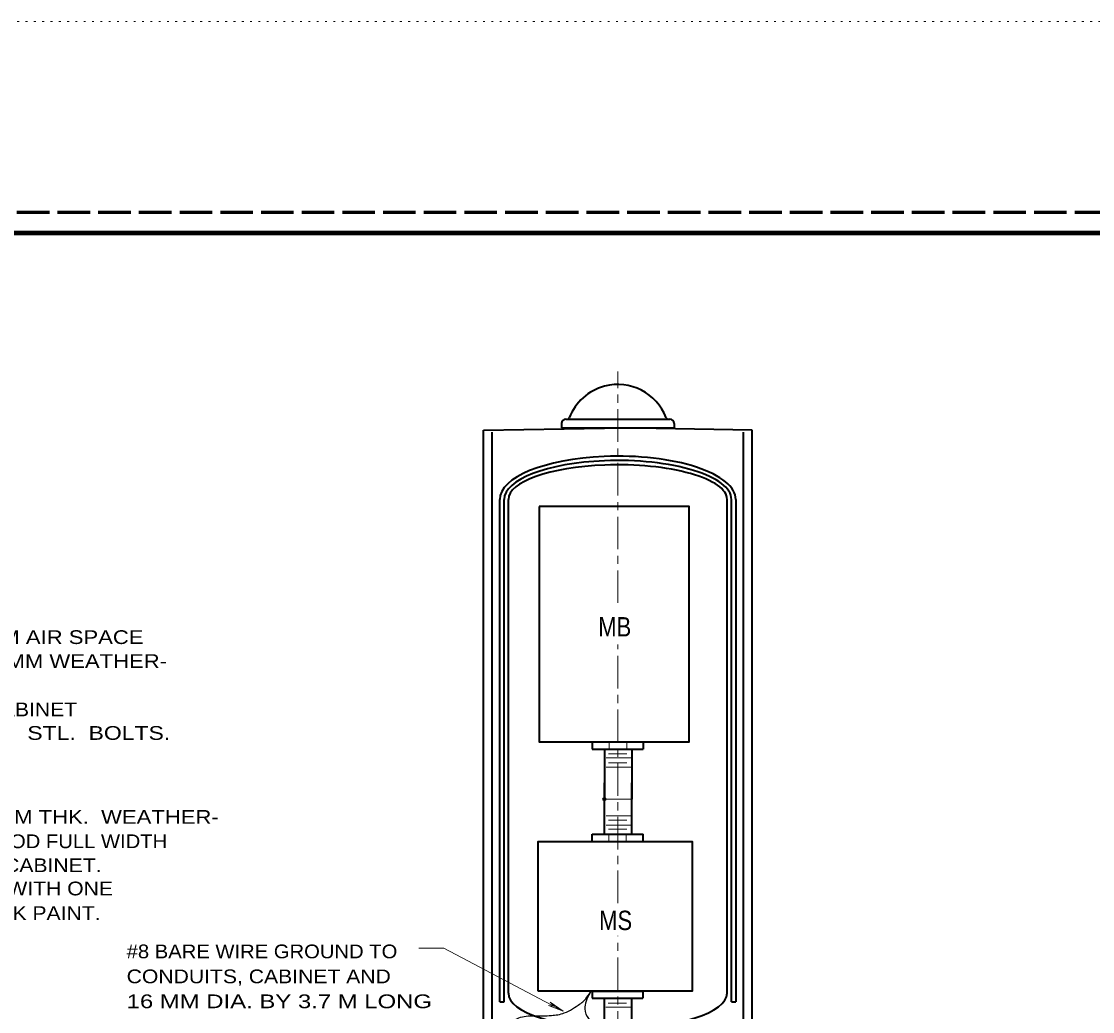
# Model space of a CAD drawing. Extents: x 312583 to 312854, y 144419 to 144597.
# Drawn here: x 312721.9 to 312781.2, y 144542 to 144596.8 of the extents above; entities that cross this region are included whole.
import ezdxf
from ezdxf.enums import TextEntityAlignment as Align

# ---------------------------------------------------------------- set-up
doc = ezdxf.new("R2010")
doc.units = 0
doc.header["$LTSCALE"] = 0.3
doc.header["$PDMODE"] = 32
doc.header["$PDSIZE"] = 0.15
for name, pattern in [('DOTTED', [1.5, 0.3, -1.2]), ('LONG_DASH_SHORT_DASH', [9.9, 6, -1.2, 1.5, -1.2]), ('LONG_DASHED', [7.5, 6, -1.5])]:
    doc.linetypes.add(name, pattern=pattern)
for name, color, linetype, lineweight in [('1', 7, 'Continuous', 25), ('2', 7, 'Continuous', 13), ('63', 7, 'DOTTED', 13)]:
    doc.layers.add(name, color=color, linetype=linetype, lineweight=lineweight)

msp = doc.modelspace()

# ---------------------------------------------------------------- linework, layer by layer
at = {"layer": '1', "linetype": 'LONG_DASHED', "lineweight": 60}
msp.add_line((312851.75, 144586.2246), (312583.526, 144586.2246), dxfattribs=at)
at = {"layer": '1', "linetype": 'LONG_DASH_SHORT_DASH', "lineweight": 13}
for p, q in [((312754.9303, 144564.6233), (312754.9303, 144577.419)), ((312754.9303, 144548.0173), (312754.9303, 144562.3156)), ((312754.9303, 144534.3093), (312754.9303, 144546.2156))]:
    msp.add_line(p, q, dxfattribs=at)
at = {"layer": '1', "lineweight": 40}
for p, q in [((312751.8176, 144574.544), (312751.8176, 144574.3063)), ((312752.0553, 144574.7893), (312752.1319, 144574.7893)), ((312752.1319, 144574.7893), (312757.7209, 144574.7893)), ((312757.7209, 144574.7893), (312757.8053, 144574.7893)), ((312758.0429, 144574.544), (312758.0429, 144574.3063)), ((312747.5013, 144574.176), (312754.2019, 144574.291)), ((312747.5013, 144536.686), (312747.5013, 144574.176)), ((312747.9843, 144539.078), (312747.9843, 144574.0686)), ((312751.8176, 144574.3063), (312754.2019, 144574.3063)), ((312751.8176, 144574.3063), (312754.2019, 144574.3063)), ((312754.2019, 144574.3063), (312758.0429, 144574.3063)), ((312762.3593, 144574.176), (312754.9303, 144574.3063)), ((312761.8763, 144547.0206), (312761.8763, 144574.0686)), ((312762.3593, 144547.0206), (312762.3593, 144574.176)), ((312748.3983, 144542.5586), (312748.3983, 144570.3426)), ((312748.6436, 144542.5586), (312748.6436, 144570.3426)), ((312748.8813, 144543.034), (312748.8813, 144570.3426)), ((312760.9793, 144543.034), (312760.9793, 144570.3426)), ((312761.2169, 144547.0206), (312761.2169, 144570.3426)), ((312761.4546, 144570.3426), (312761.4546, 144542.5586)), ((312761.2169, 144542.5586), (312761.2169, 144547.0206)), ((312761.8763, 144539.078), (312761.8763, 144547.0206)), ((312762.3593, 144536.686), (312762.3593, 144547.0206)), ((312748.3983, 144542.5586), (312748.6436, 144542.5586)), ((312761.2169, 144542.5586), (312761.4546, 144542.5586))]:
    msp.add_line(p, q, dxfattribs=at)
at = {"layer": '1', "lineweight": 35}
for p, q in [((312753.5196, 144556.949), (312756.3256, 144556.949)), ((312753.5196, 144556.949), (312753.5196, 144556.5426)), ((312756.3256, 144556.949), (312756.3256, 144556.5426)), ((312753.5196, 144556.5426), (312756.3256, 144556.5426)), ((312754.1866, 144556.5426), (312754.1866, 144553.7673)), ((312755.7046, 144556.5426), (312755.7046, 144553.7673)), ((312754.1866, 144551.8353), (312754.1866, 144554.6796)), ((312755.7046, 144551.8353), (312755.7046, 144554.6796)), ((312755.7046, 144554.6106), (312755.7046, 144554.5953)), ((312755.7046, 144553.7673), (312755.7046, 144553.7903)), ((312753.5196, 144551.8353), (312756.3256, 144551.8353)), ((312753.5196, 144551.429), (312753.5196, 144551.8353)), ((312753.5196, 144551.429), (312756.3256, 144551.429)), ((312756.3256, 144551.429), (312756.3256, 144551.8353)), ((312753.5043, 144543.1566), (312756.3179, 144543.1566)), ((312753.5043, 144543.1566), (312753.5043, 144542.758)), ((312756.3179, 144543.1566), (312756.3179, 144542.758)), ((312753.5043, 144542.758), (312756.3179, 144542.758)), ((312754.1713, 144542.758), (312754.1713, 144541.0406)), ((312755.6893, 144542.758), (312755.6893, 144541.0176))]:
    msp.add_line(p, q, dxfattribs=at)
at = {"layer": '1', "lineweight": 158}
msp.add_lwpolyline([(312616.5, 144423.1446), (312616.5, 144585.0846), (312849, 144585.0846)], dxfattribs=at)
at = {"layer": '1', "lineweight": 40}
for points in [[(312750.5756, 144569.9593), (312750.5756, 144556.9336), (312758.8709, 144556.9336), (312758.8709, 144569.9593)], [(312750.5066, 144543.172), (312759.0549, 144543.172), (312759.0549, 144551.406), (312750.5066, 144551.406)]]:
    msp.add_lwpolyline(points, close=True, dxfattribs=at)
for centre, radius, start, end in [((312754.9284, 144573.8291), 2.875, 104.68618, 158.90177), ((312754.9284, 144573.8291), 2.875, 21.1002, 104.68618), ((312752.0534, 144574.5478), 0.2396, 90, 180), ((312752.1344, 144574.9072), 0.1198, 270, 338.8998), ((312757.7223, 144574.9072), 0.1198, 201.1002, 270), ((312757.8034, 144574.5478), 0.2396, 0, 90)]:
    msp.add_arc(centre, radius, start, end, dxfattribs=at)
for centre, major_axis, ratio, start_param, end_param in [((312754.9284, 144570.3455), (6.5286, 0), 0.366972, 1.6847645, 3.1415927), ((312754.9284, 144570.3455), (6.5286, 0), 0.366972, 6.2831853, 7.9679498), ((312754.9284, 144570.3455), (6.2891, 0), 0.342857, 1.6869621, 3.1415927), ((312754.9284, 144570.3455), (6.0495, 0), 0.316832, 1.6892495, 3.1415927), ((312754.9284, 144570.3455), (6.2891, 0), 0.342857, 6.2831853, 7.9701475), ((312754.9284, 144570.3455), (6.0495, 0), 0.316832, 6.2831853, 7.9724348), ((312754.9288, 144543.033), (6.0495, 0), 0.316832, 3.1415927, 6.2831853)]:
    msp.add_ellipse(centre, major_axis=major_axis, ratio=ratio, start_param=start_param, end_param=end_param, dxfattribs=at)
at = {"layer": '1'}
msp.add_spline([(312748.3676, 144540.918), (312749.0499, 144541.4316), (312749.4563, 144541.677), (312750.2996, 144541.7843), (312751.2579, 144541.8073), (312751.9709, 144541.9453), (312752.8219, 144542.436), (312753.2896, 144542.9036), (312753.4659, 144543.172), (312753.4046, 144543.057), (312753.1133, 144542.1676), (312753.3126, 144541.631), (312753.9336, 144541.3396), (312754.2249, 144541.3626)], degree=3, dxfattribs=at)
msp.add_point((312754.1866, 144553.7673), dxfattribs=at)
at = {"layer": '2'}
for p, q in [((312754.4473, 144556.5503), (312754.4473, 144556.9336)), ((312755.4363, 144556.5273), (312755.4363, 144556.9183)), ((312754.4089, 144556.282), (312755.4363, 144556.282)), ((312754.2786, 144556.052), (312755.6586, 144556.052)), ((312754.2786, 144555.5383), (312755.6586, 144555.5383)), ((312754.4089, 144555.7836), (312755.4363, 144555.7836)), ((312754.1866, 144553.7673), (312755.7046, 144553.7673)), ((312754.1866, 144553.7673), (312755.7046, 144553.7673)), ((312754.2786, 144552.8473), (312755.6586, 144552.8473)), ((312754.4089, 144552.602), (312755.4363, 144552.602)), ((312754.2786, 144552.326), (312755.6586, 144552.326)), ((312754.4089, 144552.1036), (312755.4363, 144552.1036)), ((312754.4319, 144551.82), (312754.4319, 144551.4596)), ((312755.3903, 144551.8506), (312755.3903, 144551.406)), ((312743.922, 144545.5256), (312745.3086, 144545.5256)), ((312745.3086, 144545.5256), (312751.9096, 144542.0526)), ((312751.1966, 144542.551), (312751.3883, 144542.321)), ((312751.9096, 144542.0526), (312751.1966, 144542.551)), ((312751.0969, 144542.3593), (312751.3883, 144542.321)), ((312751.9096, 144542.0526), (312751.0969, 144542.3593)), ((312754.2633, 144542.2673), (312755.6433, 144542.2673)), ((312754.4013, 144542.4896), (312755.4209, 144542.4896))]:
    msp.add_line(p, q, dxfattribs=at)
at = {"layer": '63'}
msp.add_line((312601.2, 144596.7846), (312853.5, 144596.7846), dxfattribs=at)

# ---------------------------------------------------------------- texts
at = {"layer": '2', "width": 0.85}
for s, p in [('MB', (312754.7615, 144562.768)), ('MS', (312754.8114, 144546.53))]:
    msp.add_text(s, height=1.072, dxfattribs=at).set_placement(p, align=Align.CENTER)
at = {"layer": '2'}
for s, width, p in [('PROVIDE 6 MM AIR SPACE', 1.2, (312712.9784, 144562.3513)), ('WITH 6 BY 50 MM WEATHER-', 1.2, (312712.9931, 144561.0262)), ('FASTEN TO CABINET', 1.15, (312713.0839, 144558.3517)), ('WITH M6 STN.  STL.  BOLTS.', 1.25, (312712.9571, 144557.0506)), ('PROVIDE 20 MM THK.  WEATHER-', 1.2, (312713.0068, 144552.4101)), ('PROOF PLYWOOD FULL WIDTH', 1.1, (312712.9926, 144551.0607)), ('& LENGTH OF CABINET.', 1.15, (312712.8716, 144549.7343)), ('PAINT BOARD WITH ONE', 1.15, (312712.9218, 144548.4498)), ('COAT OF BLACK PAINT.', 1.15, (312712.8821, 144547.0863)), ('#8 BARE WIRE GROUND TO', 1.1, (312727.7681, 144544.9691)), ('CONDUITS, CABINET AND', 1.15, (312727.7681, 144543.5891)), ('16 MM DIA. BY 3.7 M LONG', 1.3, (312727.7681, 144542.2091))]:
    msp.add_text(s, height=0.76, dxfattribs=dict(at, width=width)).set_placement(p)

doc.saveas('drawing.dxf')
